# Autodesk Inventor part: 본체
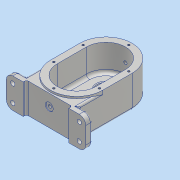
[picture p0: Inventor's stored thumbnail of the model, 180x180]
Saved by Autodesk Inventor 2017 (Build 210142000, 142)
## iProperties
Part Number: 본체
Material: 알루미늄 6061
Document SubType Name: Modeling
Designer: MRC
Density: 2.7 g/cm^3
Appearance: 알루미늄 - 평지
Mass: 756.697 g
Surface Area: 581.811 cm^2
Volume: 280.258 cm^3
Author: MRC
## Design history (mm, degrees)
sketch "스케치1"
  geometry: L1 (0, 0)-(0, 45); L2 (40, 0)-(40, 45); L3 (-40, 45)-(-40, 0); A1 r 40 centre (0, 0) between (-40, 0) and (40, 0); A2 r 40 centre (0, 45) between (40, 45) and (-40, 45); 1 further point
  constraints: 8 end point, 4 point on circle, 4 tangent, 2 centre point, 1 midpoint, 1 parallel, 1 vertical
  dimensions: "d0" = 80 distance between parallel lines of L3 L2; "d1" = 45 distance of L1.start L1.end
extrude "돌출1" new body sketch "스케치1" distance "d2" = 49; taper "d3" = 0 deg
feature "쉘1" dims "d4" = 10, "d113" = 8
sketch "스케치2"
  geometry: L1 (0, 45)-(0, 0); L2 (-26, 45)-(-26, 0); L3 (26, 0)-(26, 45); A1 r 40 centre (0, 0) between (-40, 0) and (40, 0) reference; A2 r 40 centre (0, 45) between (40, 45) and (-40, 45) reference; A3 r 26 centre (0, 45) between (26, 45) and (-26, 45); A4 r 26 centre (0, 0) between (-26, 0) and (26, 0); 1 further point
  constraints: 8 end point, 4 point on circle, 4 tangent, 2 centre point, 1 midpoint, 1 parallel, 1 vertical
  dimensions: "d5" = 52 distance between parallel lines of L3 L2
extrude "돌출2" join sketch "스케치2" distance "d6" = 11; taper "d7" = 0 deg
sketch "스케치3"
  geometry: L1 (-26, 75)-(26, 75); L2 (26, 75)-(26, 15); L3 (26, 15)-(-26, 15); L4 (-26, 15)-(-26, 75); A1 r 26 centre (0, 45) between (26, 45) and (-26, 45) reference; 2 further points
  constraints: 8 end point, 2 midpoint, 2 parallel, 1 horizontal, 1 horizontal alignment, 1 perpendicular, 1 vertical alignment
  dimensions: "d8" = 30 distance of A1.centre point (0, 15); "d9" = 52 distance of L2.end L3.end
extrude "돌출3" cut sketch "스케치3" distance "d10" = 3; taper "d11" = 0 deg
sketch "스케치4"
  geometry: A1 r 30 centre (0, -45) between (-30, -45) and (30, -45) reference; 1 further point
  constraints: 1 coincident
hole "구멍1" sketch "스케치4" at (0, -45) diameter "d12" = 20; stored, may be unused: countersink angle "d16" = 90 deg, drill point angle "d18" = 0 deg; dims "d13" = 6, "d14" = 28, "d15" = 8, "d17" = 12
sketch "스케치5"
  geometry: C1 r 14 at (0, 0); A1 r 30 centre (0, 0) between (30, 0) and (-30, 0) reference
  constraints: 1 centre point, 1 coincident
  dimensions: "d19" = 28 diameter of C1
extrude "돌출4" cut sketch "스케치5" distance "d20" = 8; taper "d21" = 0 deg
sketch "스케치6"
  geometry: A1 r 26 centre (0, 45) between (26, 45) and (-26, 45) reference; 2 further points
  constraints: 1 coincident
hole "구멍2" sketch "스케치6" at (0, 45) diameter "d22" = 22; stored, may be unused: countersink angle "d26" = 90 deg, drill point angle "d28" = 0 deg; dims "d23" = 6, "d24" = 28, "d25" = 4, "d27" = 12
sketch "스케치7"
  geometry: L1 (-61, -37)-(61, -37); L2 (61, -37)-(61, -47); L3 (61, -47)-(-61, -47); L4 (-61, -47)-(-61, -37); L5 (-40, 0)-(-40, -37); L6 (40, 0)-(40, -37); A1 r 26 centre (0, 45) between (26, 45) and (-26, 45) reference; A2 r 26 centre (0, 0) between (-26, 0) and (26, 0) reference; A3 r 40 centre (0, 0) between (-40, 0) and (40, 0) reference; 1 further point
  constraints: 12 end point, 2 parallel, 2 perpendicular, 2 point on line, 1 horizontal, 1 midpoint, 1 point on circle, 1 tangent, 1 vertical, 1 vertical alignment
  dimensions: "d29" = 10 distance of L3.end L1.start; "d30" = 47 distance from line of L3 A2.centre; "d31" = 122 distance of L2.end L3.end
extrude "돌출5" join sketch "스케치7" distance "d32" = 46; taper "d33" = 0 deg
sketch "스케치11"
  geometry: L1 (-61, -47)-(61, -47) reference; L2 (-35, -42)-(35, -42); L3 (35, -42)-(35, -47); L4 (35, -47)-(-35, -47); L5 (-35, -47)-(-35, -42); 3 further points
  constraints: 8 end point, 4 midpoint, 2 parallel, 1 horizontal, 1 perpendicular, 1 vertical alignment
  dimensions: "d39" = 5 distance of L2.end L3.end; "d40" = 70 distance of L3.end L4.end
extrude "돌출7" cut sketch "스케치11" stored distance "d41" = 38; taper "d42" = 0 deg
node "작업 평면1"
sketch "스케치12"
  geometry: C1 r 6 at (-61, 28); 1 further point
  constraints: 1 centre point
  dimensions: "d44" = 12 diameter of C1; "d45" = 21 distance of point (-61, 49) C1.centre
extrude "돌출8" join sketch "스케치12" stored distance "d46" = 12 (= d44); taper "d47" = 0 deg
sketch "스케치13"
  geometry: C1 r 6 at (0, 0) reference; 2 further points
  constraints: 1 coincident
hole "구멍3" sketch "스케치13" at (0, 0) diameter "d48" = 4.917; stored, may be unused: countersink angle "d52" = 90 deg, drill point angle "d54" = 0 deg; dims "d49" = 12, "d50" = 28, "d51" = 4, "d53" = 17.1
sketch "스케치14"
  geometry: A1 r 30 centre (0, 45) between (30, 45) and (-30, 45) reference; A2 r 30 centre (0, 0) between (-30, 0) and (30, 0) reference; 6 further points
  constraints: 4 horizontal alignment, 2 vertical alignment
  dimensions: "d55" = 35 distance of point (0, 80) A1.centre; "d56" = 35 distance of A2.centre point (0, -35); "d83" = 35 distance of point (-35, 45) A1.centre; "d84" = 35 distance of A2.centre point (-35, 0); "d85" = 35 distance of point (35, 0) A2.centre; "d86" = 35 distance of point (35, 45) A1.centre
hole "구멍4" sketch "스케치14" at (0, 80), (0, -35), (-35, 45), (-35, 0), (35, 0), (35, 45) diameter "d57" = 3.242; stored, may be unused: countersink angle "d61" = 90 deg, drill point angle "d63" = 118 deg; dims "d58" = 8, "d59" = 28, "d60" = 4, "d62" = 10
sketch "스케치15"
  geometry: C1 r 6 at (35, -18); 1 further point
  constraints: 1 centre point, 1 vertical alignment
  dimensions: "d64" = 12 diameter of C1; "d65" = 21 distance of C1.centre point (35, 3)
extrude "돌출9" cut sketch "스케치15" distance "d66" = 1; taper "d67" = 0 deg
sketch "스케치16"
  geometry: C1 r 6 at (0, 0) reference; 2 further points
  constraints: 1 coincident
hole "구멍5" sketch "스케치16" at (0, 0) diameter "d68" = 4.917; stored, may be unused: countersink angle "d72" = 90 deg, drill point angle "d74" = 0 deg; dims "d69" = 12, "d70" = 28, "d71" = 4, "d73" = 17.1
sketch "스케치17"
  geometry: C1 r 14 at (0, 45) reference; 2 further points
  constraints: 1 vertical alignment
  dimensions: "d75" = 20 distance of point (0, 65) C1.centre
hole "구멍6" sketch "스케치17" at (0, 65) diameter "d76" = 3.242; stored, may be unused: countersink angle "d80" = 90 deg, drill point angle "d82" = 118 deg; dims "d77" = 8, "d78" = 28, "d79" = 4, "d81" = 10
fillet "모깎기1" dims "d87" = 10
fillet "모깎기2" dims "d88" = 3, "d112" = 5
chamfer "모따기1" distance "d89" = 1; stored, may be unused: second distance "d90" = 2, angle "d91" = 45 deg
fillet "모깎기3" dims "d92" = 0.3, "d93" = 3
chamfer "모따기2" distance "d94" = 1; stored, may be unused: second distance "d95" = 2, angle "d96" = 45 deg
sketch "스케치18"
  geometry: A1 r 7 centre (11, 7) between (11, 0) and (18, 7) reference; A2 r 7 centre (11, 33) between (18, 33) and (11, 40) reference; 3 further points
  constraints: 2 coincident
hole "구멍7" sketch "스케치18" at (11, 7), (11, 33) diameter "d97" = 6.6; stored, may be unused: countersink angle "d101" = 90 deg, drill point angle "d103" = 118 deg; dims "d98" = 6.6, "d99" = 11, "d100" = 2, "d102" = 10
fillet "모깎기4" dims "d104" = 3
sketch "스케치19"
  geometry: L1 (-35, -47)-(-51, -47) reference; A1 r 37 centre (0, 45) between (37, 45) and (-37, 45) reference; 1 further point
  constraints: 1 vertical alignment, 1 other
  dimensions: "d105" = 12 distance from line of point (0, -35) L1
feature "엠보싱1" sketch "스케치19" dims "d0" = 80, "d1" = 45, "d106" = 0.5, "d107" = 0
chamfer "모따기3" distance "d108" = 1; stored, may be unused: second distance "d109" = 2, angle "d110" = 45 deg
fillet "모깎기5" dims "d111" = 3
fillet "모깎기6" dims "d117" = 3
fillet "모깎기7" dims "d118" = 3
node "솔리드1"
mirror "미러1"
pattern_circular "원형 패턴1" dims angle "d115" = 360 deg
other parameters: "d43" = -135
